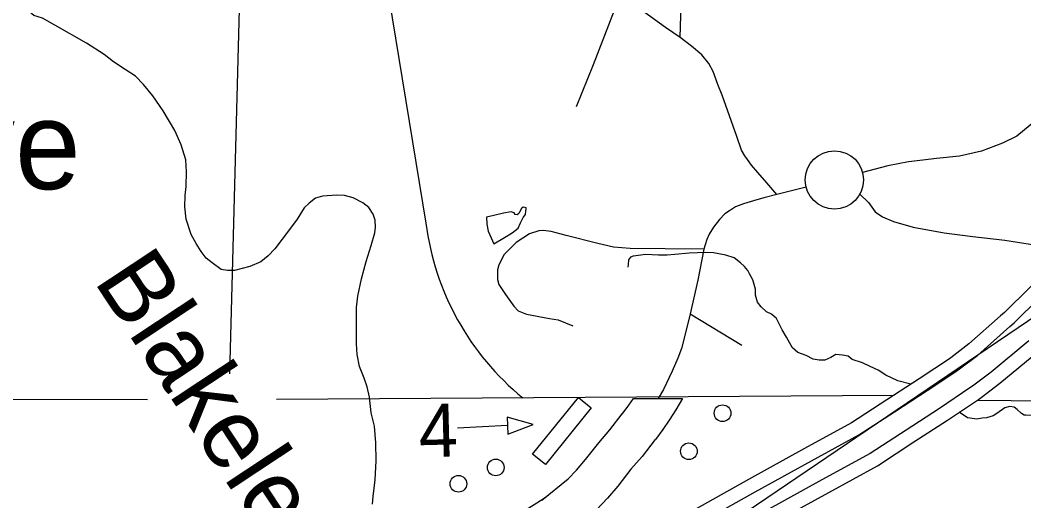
# Model space of a CAD drawing. Extents: x 22866 to 28196, y 1324810 to 1328105.
# Drawn here: x 25058.2 to 25202.6, y 1326013.1 to 1326082.2 of the extents above; entities that cross this region are included whole.
import ezdxf

# ---------------------------------------------------------------- set-up
doc = ezdxf.new("R2010")
doc.units = 0
for name, color, linetype in [('Level 10', 7, 'Continuous'), ('Level 19', 7, 'Continuous'), ('Level 24', 7, 'Continuous'), ('Level 31', 7, 'Continuous'), ('Level 32', 7, 'Continuous'), ('Level 35', 7, 'Continuous'), ('Level 5', 7, 'Continuous'), ('Level 56', 7, 'Continuous'), ('Level 63', 7, 'Continuous'), ('Page Text', 7, 'Continuous')]:
    doc.layers.add(name, color=color, linetype=linetype)

msp = doc.modelspace()

# ---------------------------------------------------------------- linework, layer by layer
at = {"layer": 'Level 10'}
msp.add_line((25133.83, 1326013.65), (25133.25, 1326013.24), dxfattribs=at)
for points in [[(25210.02, 1326073.03), (25207.14, 1326070.24), (25206.41, 1326069.52), (25203.52, 1326067.13), (25201.59, 1326065.55), (25199.5, 1326064.53), (25196.51, 1326063.42), (25193.32, 1326062.67), (25190.05, 1326062.36), (25188.08, 1326062.12), (25185.99, 1326061.89), (25183.04, 1326061.3), (25179.4, 1326060.35)], [(25171.27, 1326058.24), (25167.05, 1326057.18)], [(25167.05, 1326057.18), (25165.19, 1326056.68), (25163.72, 1326056.26), (25162.25, 1326055.83), (25161.1, 1326055.38), (25160.26, 1326054.84), (25159.59, 1326054.37), (25158.8, 1326053.56), (25157.93, 1326052.48), (25157.32, 1326051.49), (25156.99, 1326050.7), (25156.75, 1326049.95), (25156.57, 1326049.3)], [(25156.57, 1326049.3), (25155.69, 1326044.86), (25154.58, 1326040.02), (25153.72, 1326036.53), (25153.33, 1326035.05), (25152.8, 1326033.65), (25152.01, 1326031.78), (25150.77, 1326029.15), (25149.99, 1326027.86)], [(25144.82, 1326025.61), (25145.79, 1326026.88), (25146.46, 1326027.87)], [(25146.43, 1326027.83), (25153.48, 1326027.85), (25152.52, 1326026.24), (25151.58, 1326024.74), (25150.67, 1326023.38), (25149.59, 1326021.97)], [(25133.25, 1326013.24), (25137.05, 1326016.29), (25138.27, 1326017.56), (25139.55, 1326019.06), (25141.45, 1326021.49), (25143.06, 1326023.34), (25144.83, 1326025.63)], [(25149.57, 1326021.95), (25147.7, 1326019.53), (25146.08, 1326017.67), (25144.2, 1326015.26), (25142.72, 1326013.53), (25141.11, 1326011.85), (25137.01, 1326008.56)], [(25117.36, 1325996.23), (25113.59, 1326000.91), (25114.42, 1326001.58), (25116.66, 1326003.1), (25119.07, 1326004.6), (25123.16, 1326006.96), (25133.83, 1326013.65)]]:
    msp.add_lwpolyline(points, dxfattribs=at)
at = {"layer": 'Level 19'}
for points in [[(25217.23, 1326053.95), (25215.9, 1326055.51), (25210.71, 1326050.65), (25203.44, 1326043.8), (25199.8, 1326040.22), (25199.23, 1326039.73)], [(25200.56, 1326038.18), (25201.18, 1326038.71), (25204.85, 1326042.33), (25212.11, 1326049.16), (25217.23, 1326053.96)], [(25199.23, 1326039.73), (25194.69, 1326035.69), (25192.1, 1326033.71)], [(25193.34, 1326032.09), (25195.96, 1326034.09), (25200.56, 1326038.18)], [(25203.3, 1326036.12), (25197.89, 1326031.64), (25195.23, 1326029.61)], [(25196.47, 1326027.98), (25199.16, 1326030.04), (25204.6, 1326034.55)], [(25192.15, 1326033.75), (25192.04, 1326033.66), (25187.56, 1326030.67), (25182.87, 1326027.65), (25177.82, 1326024.37), (25171.06, 1326020.68), (25162.98, 1326016.21), (25155.14, 1326011.81), (25149.1, 1326008.24), (25147.14, 1326007.25), (25142, 1326004.42), (25135.83, 1326000.97), (25129.04, 1325997.04), (25122.06, 1325992.82), (25117.06, 1325989.29)], [(25118.3, 1325987.67), (25123.17, 1325991.11), (25130.08, 1325995.28), (25136.84, 1325999.19), (25142.99, 1326002.63), (25148.09, 1326005.44), (25150.08, 1326006.46), (25156.16, 1326010.05), (25163.97, 1326014.43), (25172.05, 1326018.89), (25178.87, 1326022.62), (25183.98, 1326025.93), (25188.71, 1326028.99), (25192.82, 1326031.72), (25193.34, 1326032.09)], [(25195.23, 1326029.61), (25194.83, 1326029.36), (25190.47, 1326026.41), (25185.67, 1326023.31), (25180.47, 1326019.93), (25173.55, 1326016.15), (25165.49, 1326011.7), (25157.71, 1326007.34), (25151.59, 1326003.72), (25149.56, 1326002.69), (25144.5, 1325999.9), (25138.38, 1325996.48), (25131.67, 1325992.59), (25124.88, 1325988.49), (25120.2, 1325985.19)], [(25121.44, 1325983.57), (25126, 1325986.78), (25132.71, 1325990.84), (25139.39, 1325994.71), (25145.49, 1325998.12), (25150.51, 1326000.88), (25152.57, 1326001.93), (25158.73, 1326005.57), (25166.48, 1326009.92), (25174.53, 1326014.36), (25181.52, 1326018.18), (25186.78, 1326021.6), (25191.62, 1326024.72), (25196.08, 1326027.71), (25196.47, 1326027.98)]]:
    msp.add_lwpolyline(points, dxfattribs=at)
at = {"layer": 'Level 24'}
msp.add_circle((25175.34, 1326059.26), 4.2, dxfattribs=at)
at = {"layer": 'Level 31'}
for points in [[(25153.15, 1326079.73), (25153.33, 1326086.17), (25153.57, 1326090.76), (25153.68, 1326098.01), (25153.92, 1326106.72)], [(25153.15, 1326079.73), (25151.03, 1326081.16), (25148.44, 1326083.02), (25144.54, 1326085.84), (25140.41, 1326089.55)], [(25159.22, 1326071.44), (25158.59, 1326072.97), (25157.9, 1326074.83), (25157.26, 1326075.99), (25156.26, 1326077.23), (25154.81, 1326078.49), (25153.15, 1326079.73)], [(25167.05, 1326057.18), (25165.62, 1326058.86), (25164.34, 1326060.32), (25163.41, 1326061.39), (25162.84, 1326062.2), (25162.46, 1326062.72), (25161.98, 1326063.53), (25161.29, 1326065.52), (25159.22, 1326071.44)], [(25179.02, 1326057.24), (25180.25, 1326056.01), (25181.22, 1326054.69), (25182.26, 1326053.97), (25183.85, 1326053.31), (25186.68, 1326052.48), (25191.14, 1326051.65)], [(25191.14, 1326051.65), (25195.24, 1326051.11), (25199.84, 1326050.59), (25206.23, 1326049.62), (25207.93, 1326049.31)]]:
    msp.add_lwpolyline(points, dxfattribs=at)
at = {"layer": 'Level 32'}
for points in [[(25138.27, 1326069.82), (25140.67, 1326075.86), (25144.54, 1326085.84), (25144.54, 1326085.84)], [(25156.57, 1326049.3), (25151.01, 1326049.37), (25145.95, 1326049.41), (25143.55, 1326049.58), (25141.32, 1326050.14), (25136.78, 1326051.29), (25134.59, 1326051.85), (25133.44, 1326051.99), (25132.81, 1326051.96), (25131.48, 1326051.5), (25129.57, 1326050.28), (25127.86, 1326048.57), (25127.06, 1326047.07), (25126.88, 1326046.34), (25126.88, 1326044.94), (25127.09, 1326044.24), (25128.03, 1326042.78), (25129.22, 1326041.1), (25129.85, 1326040.44), (25131.07, 1326039.95), (25134.34, 1326039.36)], [(25134.34, 1326039.36), (25135.6, 1326039.16), (25137.73, 1326038.29)], [(25154.58, 1326040.02), (25162.05, 1326035.52)]]:
    msp.add_lwpolyline(points, dxfattribs=at)
at = {"layer": 'Level 35'}
for points in [[(25063.19, 1326081.5), (25061.42, 1326082.53), (25060.17, 1326082.9), (25059.57, 1326083.42), (25059.1, 1326084.23), (25059.07, 1326084.86), (25058.89, 1326086.01), (25058.62, 1326086.95), (25058.42, 1326087.58)], [(25096.95, 1326052.15), (25094.84, 1326049.37), (25093.88, 1326048.35), (25092.83, 1326047.49), (25091.24, 1326046.84), (25089.07, 1326046.23), (25088.07, 1326046.23), (25087.13, 1326046.39), (25085.85, 1326047.36), (25084.99, 1326048.01), (25084.26, 1326048.96), (25083.55, 1326050.11), (25082.82, 1326051.41), (25082.09, 1326053.61), (25081.93, 1326055.42), (25081.98, 1326057.04), (25082.11, 1326058.31), (25082.17, 1326060.45), (25082.03, 1326062.15), (25081.38, 1326064.32), (25080.47, 1326066.39), (25078.79, 1326069.19), (25077.33, 1326071.34), (25075.95, 1326073), (25074.8, 1326074.17), (25073.34, 1326075.12), (25071.66, 1326076.24), (25070.3, 1326077.31), (25067.77, 1326078.91), (25063.19, 1326081.5)], [(25108.89, 1326012.68), (25109.02, 1326013.76), (25109.31, 1326016.14), (25109.42, 1326018.89), (25109.39, 1326021.48), (25109.18, 1326023.88), (25108.69, 1326025.79), (25108.45, 1326028.02), (25108.16, 1326029.51), (25107.69, 1326030.79), (25107.04, 1326032.47), (25106.72, 1326034.17), (25106.59, 1326035.69), (25106.59, 1326037.57), (25106.59, 1326039.56), (25106.59, 1326040.94), (25106.78, 1326042.54), (25107.3, 1326045.06), (25108.01, 1326047.54), (25108.69, 1326049.82), (25109.26, 1326051.65), (25109.34, 1326052.46), (25109.29, 1326053.46), (25109.02, 1326054.35), (25108.37, 1326055.29), (25107.51, 1326055.99), (25106.1, 1326056.67), (25104.87, 1326057.04), (25103.77, 1326057.07), (25101.73, 1326056.94), (25100.71, 1326056.65), (25099.8, 1326055.91), (25099.07, 1326055.26), (25098.07, 1326053.61), (25096.95, 1326052.15)], [(25126.34, 1326050.09), (25127.88, 1326051), (25129.01, 1326051.68), (25129.84, 1326052.34), (25130.21, 1326053.12), (25130.58, 1326053.85), (25130.92, 1326054.3), (25130.94, 1326054.77), (25131.02, 1326055.11), (25130.99, 1326055.27), (25130.81, 1326055.32), (25130.58, 1326055.34), (25130.34, 1326055.16), (25130.05, 1326054.64), (25129.95, 1326054.45), (25129.69, 1326054.27), (25129.43, 1326054.3), (25129.27, 1326054.53), (25128.85, 1326054.66), (25127.75, 1326054.51), (25126.34, 1326054.17), (25125.32, 1326053.91)], [(25125.32, 1326053.91), (25125.35, 1326052.89), (25125.53, 1326051.92), (25125.95, 1326050.92), (25126.34, 1326050.09)], [(25146.42, 1326048.31), (25146, 1326048.15), (25145.71, 1326047.76), (25145.66, 1326047.13), (25145.61, 1326046.71)], [(25148.22, 1326048.54), (25146.42, 1326048.31), (25146.26, 1326048.28)], [(25160.91, 1326048.08), (25159.75, 1326048.46), (25157.94, 1326048.78), (25156.87, 1326048.83), (25154.47, 1326048.73), (25152.4, 1326048.54), (25151.3, 1326048.44), (25150.05, 1326048.44), (25148.22, 1326048.54)], [(25172.3, 1326033.52), (25171.29, 1326034.03), (25170.09, 1326034.48), (25169.31, 1326035.13), (25168.91, 1326035.81), (25168.44, 1326036.68), (25167.82, 1326037.72), (25167.03, 1326039.35), (25166.3, 1326039.95), (25165.59, 1326040.31), (25164.81, 1326041.02), (25164.29, 1326041.7), (25164, 1326042.69), (25164, 1326043.56), (25163.61, 1326044.89), (25163.14, 1326045.78), (25162.88, 1326046.25), (25162.4, 1326046.83), (25161.86, 1326047.35), (25160.91, 1326048.08)], [(25186.36, 1326029.9), (25184.46, 1326030.39), (25182.73, 1326031.2), (25181.66, 1326031.9), (25180.48, 1326032.45), (25179.39, 1326032.98), (25177.92, 1326033.45), (25177.32, 1326033.92), (25176.49, 1326034.07), (25175.57, 1326034.15), (25174.84, 1326033.76), (25173.98, 1326033.34), (25173.17, 1326033.37), (25172.3, 1326033.52)], [(25195.83, 1326024.9), (25194.47, 1326025.07), (25193.31, 1326025.86)], [(25211.58, 1326020.52), (25211.24, 1326021.16), (25210.95, 1326022.41), (25210.43, 1326023.07), (25209.54, 1326023.85), (25208.36, 1326024.43), (25207.29, 1326024.82), (25206.09, 1326025.08), (25204.78, 1326025.42), (25203.82, 1326025.42), (25202.9, 1326025.45), (25202.62, 1326025.47), (25202.26, 1326025.68), (25201.63, 1326026.26), (25201.18, 1326026.6), (25200.58, 1326026.68), (25199.88, 1326026.52), (25198.7, 1326025.68), (25198.18, 1326025.34), (25197.21, 1326025.06), (25196.61, 1326025), (25195.83, 1326024.9)]]:
    msp.add_lwpolyline(points, dxfattribs=at)
at = {"layer": 'Level 5'}
for points in [[(25088.36, 1326031.4), (25091.03, 1326130.86)], [(25076.56, 1326027.67), (25042.45, 1326027.72)], [(25183.88, 1326028.3), (25095.08, 1326027.7)], [(25215.34, 1326027.37), (25195.93, 1326027.57)]]:
    msp.add_lwpolyline(points, dxfattribs=at)
at = {"layer": 'Level 56'}
msp.add_line((25128.32, 1326023.96), (25121.12, 1326023.58), dxfattribs=at)
for points in [[(25138.52, 1326028), (25140.38, 1326026.49), (25133.77, 1326018.34), (25131.9, 1326019.85)], [(25128.29, 1326025.17), (25128.39, 1326022.72), (25132.01, 1326024.1)]]:
    msp.add_lwpolyline(points, close=True, dxfattribs=at)
for centre in [(25159.25, 1326025.73), (25154.41, 1326020.26), (25126.63, 1326017.94), (25121.26, 1326015.59)]:
    msp.add_circle(centre, 1.2, dxfattribs=at)
at = {"layer": 'Level 63'}
msp.add_line((25111.19, 1326085.82), (25116.58, 1326053.07), dxfattribs=at)
msp.add_arc((25155.05, 1326057.99), 38.78, 187.283, 230.7808, dxfattribs=at)
at = {"layer": 'Page Text'}
msp.add_lwpolyline([(25237.8, 1326062.38), (24752.99, 1325734.09)], dxfattribs=at)

# ---------------------------------------------------------------- texts
at = {"layer": 'Level 24'}
msp.add_text('Grove', height=12.674, dxfattribs=at).set_placement((25020.77, 1326057.94))
at = {"layer": 'Level 35'}
msp.add_text('Blakeley', height=10.139, rotation=303.4695, dxfattribs=at).set_placement((25068.68, 1326044.8))
at = {"layer": 'Level 56'}
msp.add_text('4', height=7.6, rotation=1.4702, dxfattribs=at).set_placement((25115.63, 1326019.4))

doc.saveas('drawing.dxf')
